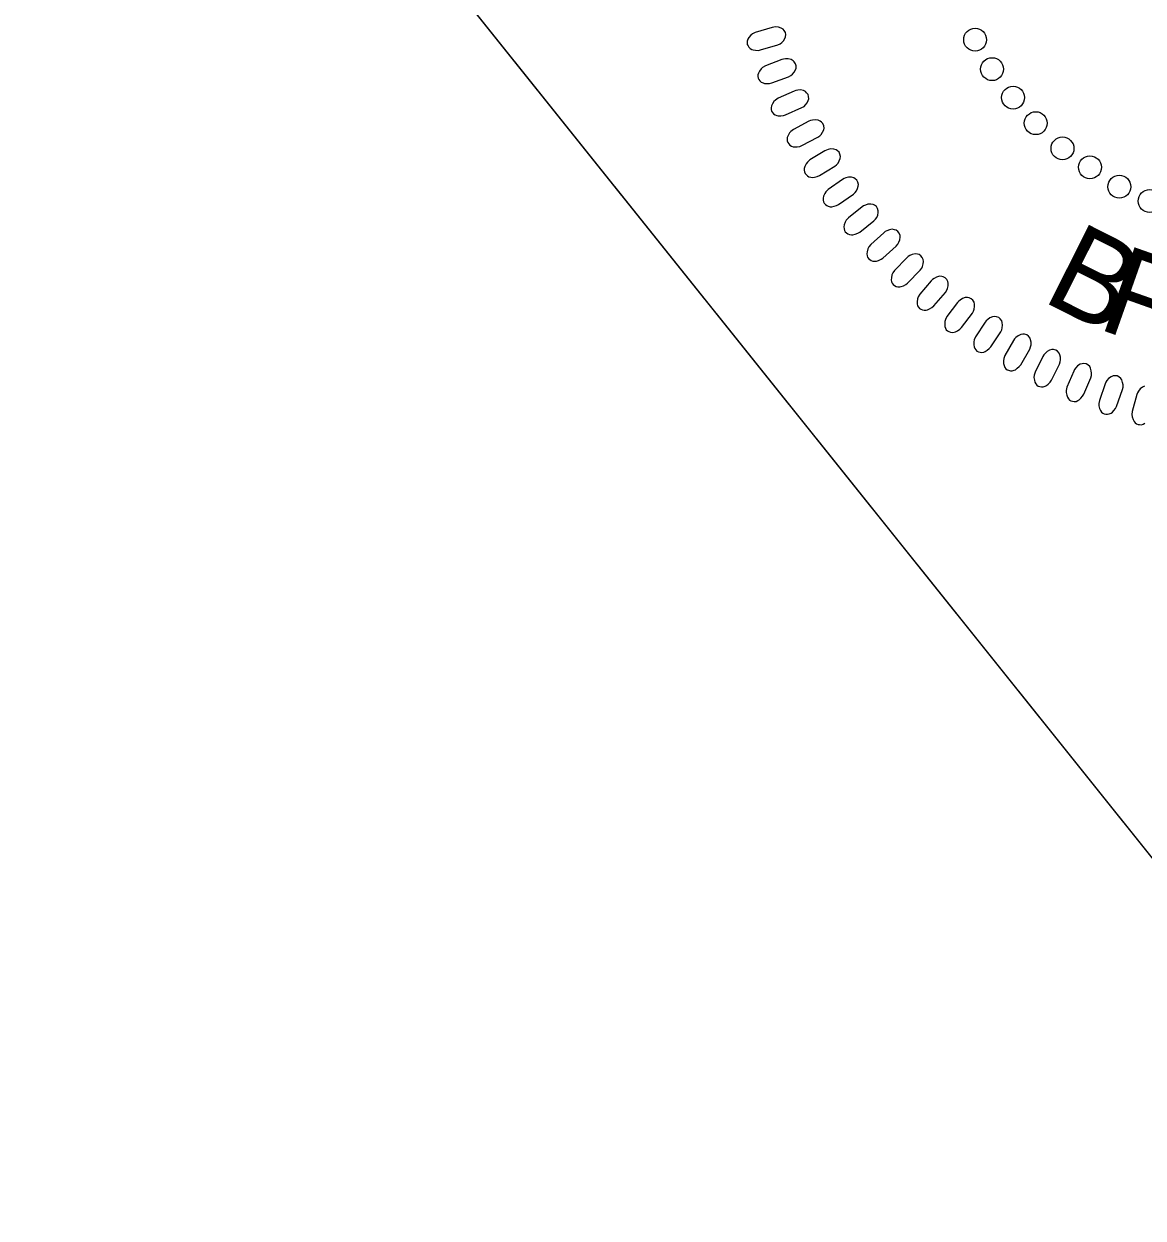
# Model space of a CAD drawing. Extents: x 473546 to 475544, y 505920 to 507827.
# Drawn here: x 474718.5 to 474796.9, y 507532.4 to 507616 of the extents above; entities that cross this region are included whole.
import ezdxf

# ---------------------------------------------------------------- set-up
doc = ezdxf.new("R2010")
doc.units = 0
for name, color, linetype in [('Sheet Clip Boundary CELL', 7, 'Continuous'), ('Sheet Plan CELL', 7, 'Continuous'), ('Sheet Profile Grid Minor CELL', 7, 'Continuous')]:
    doc.layers.add(name, color=color, linetype=linetype)

msp = doc.modelspace()

# ---------------------------------------------------------------- linework, layer by layer
at = {"layer": 'Sheet Clip Boundary CELL'}
msp.add_lwpolyline([(474813.139, 507538.121), (474704.643, 507673.668), (473746.994, 506907.144), (474401.701, 506086.253), (475384.175, 506871.789), (475333.837, 506934.746), (475466.728, 507040.999), (474969.31, 507663.123)], close=True, dxfattribs=at)
at = {"layer": 'Sheet Plan CELL'}
msp.add_lwpolyline([(474728.157, 507644.284), (474806.271, 507706.801), (474876.574, 507618.957), (474798.455, 507556.468)], close=True, dxfattribs=at)
at = {"layer": 'Sheet Profile Grid Minor CELL'}
for points in [[(474770.907, 507615.766), (474769.735, 507615.407), (474769.536, 507615.306), (474769.418, 507615.216), (474769.288, 507615.059), (474769.212, 507614.934), (474769.169, 507614.803), (474769.162, 507614.691), (474769.175, 507614.578), (474769.227, 507614.477), (474769.291, 507614.371), (474769.378, 507614.289), (474769.504, 507614.218), (474769.598, 507614.184), (474769.761, 507614.164), (474769.95, 507614.16), (474770.109, 507614.185), (474771.313, 507614.546), (474771.468, 507614.617), (474771.589, 507614.701), (474771.715, 507614.833), (474771.816, 507614.982), (474771.863, 507615.098), (474771.875, 507615.266), (474771.85, 507615.414), (474771.768, 507615.545), (474771.689, 507615.631), (474771.557, 507615.723), (474771.36, 507615.787), (474771.168, 507615.799), (474771.035, 507615.79)], [(474771.592, 507613.51), (474770.444, 507613.077), (474770.252, 507612.964), (474770.139, 507612.867), (474770.02, 507612.702), (474769.952, 507612.572), (474769.917, 507612.439), (474769.916, 507612.328), (474769.938, 507612.215), (474769.996, 507612.118), (474770.066, 507612.016), (474770.158, 507611.94), (474770.289, 507611.876), (474770.385, 507611.849), (474770.549, 507611.838), (474770.737, 507611.846), (474770.894, 507611.881), (474772.073, 507612.317), (474772.224, 507612.398), (474772.339, 507612.49), (474772.456, 507612.63), (474772.547, 507612.784), (474772.588, 507612.903), (474772.589, 507613.071), (474772.554, 507613.218), (474772.464, 507613.344), (474772.381, 507613.423), (474772.243, 507613.508), (474772.042, 507613.56), (474771.85, 507613.559), (474771.718, 507613.542)], [(474772.451, 507611.309), (474771.332, 507610.804), (474771.148, 507610.68), (474771.041, 507610.576), (474770.933, 507610.404), (474770.873, 507610.27), (474770.846, 507610.135), (474770.853, 507610.023), (474770.881, 507609.912), (474770.945, 507609.819), (474771.022, 507609.722), (474771.119, 507609.651), (474771.253, 507609.597), (474771.35, 507609.575), (474771.515, 507609.575), (474771.703, 507609.594), (474771.857, 507609.639), (474773.006, 507610.148), (474773.152, 507610.239), (474773.26, 507610.337), (474773.369, 507610.484), (474773.45, 507610.643), (474773.483, 507610.765), (474773.473, 507610.933), (474773.43, 507611.077), (474773.332, 507611.197), (474773.244, 507611.272), (474773.101, 507611.347), (474772.897, 507611.387), (474772.706, 507611.374), (474772.575, 507611.348)], [(474773.486, 507609.197), (474772.402, 507608.624), (474772.225, 507608.488), (474772.126, 507608.377), (474772.028, 507608.198), (474771.977, 507608.061), (474771.959, 507607.924), (474771.972, 507607.814), (474772.007, 507607.705), (474772.077, 507607.616), (474772.159, 507607.524), (474772.261, 507607.459), (474772.398, 507607.413), (474772.497, 507607.398), (474772.661, 507607.408), (474772.847, 507607.439), (474772.999, 507607.493), (474774.114, 507608.074), (474774.253, 507608.173), (474774.355, 507608.279), (474774.454, 507608.432), (474774.526, 507608.596), (474774.55, 507608.72), (474774.53, 507608.886), (474774.478, 507609.028), (474774.373, 507609.142), (474774.28, 507609.21), (474774.132, 507609.277), (474773.927, 507609.303), (474773.736, 507609.279), (474773.607, 507609.244)], [(474774.604, 507607.127), (474773.558, 507606.487), (474773.39, 507606.341), (474773.298, 507606.224), (474773.212, 507606.039), (474773.169, 507605.899), (474773.159, 507605.762), (474773.18, 507605.652), (474773.222, 507605.545), (474773.297, 507605.461), (474773.385, 507605.374), (474773.491, 507605.316), (474773.631, 507605.279), (474773.73, 507605.27), (474773.893, 507605.29), (474774.077, 507605.333), (474774.225, 507605.397), (474775.301, 507606.046), (474775.434, 507606.154), (474775.529, 507606.265), (474775.618, 507606.424), (474775.679, 507606.593), (474775.696, 507606.718), (474775.666, 507606.883), (474775.604, 507607.021), (474775.492, 507607.127), (474775.395, 507607.191), (474775.244, 507607.247), (474775.037, 507607.261), (474774.848, 507607.224), (474774.723, 507607.182)], [(474775.845, 507605.118), (474774.841, 507604.414), (474774.683, 507604.257), (474774.598, 507604.134), (474774.524, 507603.945), (474774.489, 507603.802), (474774.489, 507603.665), (474774.516, 507603.556), (474774.564, 507603.453), (474774.645, 507603.373), (474774.739, 507603.292), (474774.847, 507603.24), (474774.989, 507603.212), (474775.089, 507603.209), (474775.25, 507603.24), (474775.431, 507603.294), (474775.575, 507603.367), (474776.608, 507604.083), (474776.734, 507604.199), (474776.822, 507604.315), (474776.901, 507604.481), (474776.951, 507604.652), (474776.961, 507604.778), (474776.92, 507604.941), (474776.85, 507605.075), (474776.732, 507605.174), (474776.63, 507605.231), (474776.476, 507605.278), (474776.269, 507605.278), (474776.083, 507605.231), (474775.96, 507605.18)], [(474777.213, 507603.202), (474776.255, 507602.435), (474776.107, 507602.269), (474776.03, 507602.141), (474775.968, 507601.948), (474775.943, 507601.803), (474775.951, 507601.666), (474775.985, 507601.559), (474776.039, 507601.459), (474776.125, 507601.384), (474776.223, 507601.309), (474776.335, 507601.265), (474776.478, 507601.246), (474776.578, 507601.249), (474776.737, 507601.289), (474776.914, 507601.355), (474777.053, 507601.437), (474778.039, 507602.216), (474778.157, 507602.339), (474778.238, 507602.462), (474778.307, 507602.632), (474778.346, 507602.806), (474778.348, 507602.932), (474778.296, 507603.092), (474778.218, 507603.221), (474778.094, 507603.313), (474777.989, 507603.363), (474777.832, 507603.401), (474777.625, 507603.388), (474777.443, 507603.328), (474777.323, 507603.271)], [(474778.727, 507601.394), (474777.818, 507600.569), (474777.681, 507600.394), (474777.613, 507600.261), (474777.563, 507600.064), (474777.547, 507599.918), (474777.563, 507599.781), (474777.604, 507599.678), (474777.665, 507599.581), (474777.755, 507599.512), (474777.858, 507599.443), (474777.972, 507599.406), (474778.117, 507599.396), (474778.216, 507599.405), (474778.371, 507599.456), (474778.545, 507599.532), (474778.678, 507599.622), (474779.613, 507600.462), (474779.724, 507600.593), (474779.796, 507600.72), (474779.854, 507600.894), (474779.882, 507601.07), (474779.876, 507601.196), (474779.815, 507601.352), (474779.729, 507601.476), (474779.599, 507601.56), (474779.492, 507601.604), (474779.332, 507601.631), (474779.127, 507601.606), (474778.948, 507601.535), (474778.832, 507601.47)], [(474780.343, 507599.638), (474779.488, 507598.757), (474779.363, 507598.574), (474779.302, 507598.437), (474779.265, 507598.237), (474779.258, 507598.091), (474779.283, 507597.955), (474779.331, 507597.854), (474779.398, 507597.761), (474779.492, 507597.698), (474779.598, 507597.636), (474779.715, 507597.606), (474779.86, 507597.605), (474779.959, 507597.621), (474780.11, 507597.681), (474780.279, 507597.768), (474780.406, 507597.867), (474781.287, 507598.763), (474781.388, 507598.9), (474781.453, 507599.032), (474781.5, 507599.209), (474781.517, 507599.387), (474781.503, 507599.512), (474781.432, 507599.665), (474781.338, 507599.783), (474781.203, 507599.859), (474781.094, 507599.895), (474780.933, 507599.913), (474780.729, 507599.874), (474780.556, 507599.792), (474780.444, 507599.72)], [(474782.056, 507598.03), (474781.259, 507597.098), (474781.145, 507596.907), (474781.093, 507596.768), (474781.068, 507596.565), (474781.071, 507596.419), (474781.104, 507596.285), (474781.158, 507596.187), (474781.23, 507596.099), (474781.328, 507596.041), (474781.439, 507595.987), (474781.557, 507595.963), (474781.701, 507595.972), (474781.799, 507595.993), (474781.947, 507596.063), (474782.11, 507596.161), (474782.23, 507596.267), (474783.053, 507597.217), (474783.145, 507597.361), (474783.203, 507597.496), (474783.238, 507597.675), (474783.244, 507597.855), (474783.222, 507597.978), (474783.141, 507598.125), (474783.04, 507598.238), (474782.901, 507598.305), (474782.789, 507598.335), (474782.628, 507598.342), (474782.427, 507598.291), (474782.258, 507598.198), (474782.152, 507598.119)], [(474783.894, 507596.502), (474783.156, 507595.522), (474783.055, 507595.324), (474783.012, 507595.181), (474783, 507594.978), (474783.011, 507594.832), (474783.053, 507594.701), (474783.113, 507594.606), (474783.191, 507594.523), (474783.292, 507594.471), (474783.405, 507594.424), (474783.525, 507594.408), (474783.669, 507594.425), (474783.765, 507594.453), (474783.908, 507594.532), (474784.064, 507594.64), (474784.178, 507594.753), (474784.939, 507595.753), (474785.023, 507595.902), (474785.071, 507596.041), (474785.095, 507596.222), (474785.09, 507596.401), (474785.06, 507596.523), (474784.97, 507596.666), (474784.863, 507596.771), (474784.719, 507596.829), (474784.606, 507596.852), (474784.444, 507596.849), (474784.247, 507596.785), (474784.085, 507596.682), (474783.984, 507596.596)], [(474785.831, 507595.128), (474785.157, 507594.103), (474785.068, 507593.899), (474785.034, 507593.754), (474785.035, 507593.55), (474785.056, 507593.405), (474785.106, 507593.277), (474785.171, 507593.186), (474785.254, 507593.108), (474785.358, 507593.063), (474785.475, 507593.022), (474785.595, 507593.015), (474785.737, 507593.041), (474785.831, 507593.074), (474785.969, 507593.162), (474786.118, 507593.279), (474786.225, 507593.4), (474786.922, 507594.446), (474786.996, 507594.6), (474787.035, 507594.741), (474787.048, 507594.923), (474787.031, 507595.102), (474786.994, 507595.222), (474786.895, 507595.358), (474786.781, 507595.457), (474786.635, 507595.506), (474786.52, 507595.522), (474786.359, 507595.509), (474786.166, 507595.432), (474786.011, 507595.32), (474785.915, 507595.227)], [(474787.822, 507593.855), (474787.213, 507592.79), (474787.136, 507592.58), (474787.112, 507592.433), (474787.125, 507592.231), (474787.156, 507592.087), (474787.214, 507591.962), (474787.284, 507591.876), (474787.372, 507591.803), (474787.478, 507591.765), (474787.598, 507591.731), (474787.718, 507591.731), (474787.858, 507591.766), (474787.95, 507591.806), (474788.083, 507591.902), (474788.223, 507592.028), (474788.322, 507592.156), (474788.952, 507593.243), (474789.017, 507593.401), (474789.047, 507593.545), (474789.049, 507593.728), (474789.02, 507593.905), (474788.976, 507594.022), (474788.869, 507594.152), (474788.749, 507594.244), (474788.6, 507594.283), (474788.484, 507594.291), (474788.324, 507594.268), (474788.137, 507594.18), (474787.989, 507594.058), (474787.899, 507593.96)], [(474789.873, 507592.731), (474789.332, 507591.63), (474789.269, 507591.417), (474789.254, 507591.268), (474789.281, 507591.066), (474789.32, 507590.925), (474789.385, 507590.804), (474789.462, 507590.722), (474789.553, 507590.655), (474789.663, 507590.624), (474789.784, 507590.598), (474789.904, 507590.605), (474790.042, 507590.649), (474790.13, 507590.694), (474790.257, 507590.798), (474790.389, 507590.934), (474790.48, 507591.067), (474791.041, 507592.191), (474791.095, 507592.354), (474791.116, 507592.498), (474791.106, 507592.681), (474791.068, 507592.856), (474791.015, 507592.971), (474790.9, 507593.094), (474790.775, 507593.178), (474790.623, 507593.207), (474790.507, 507593.208), (474790.349, 507593.175), (474790.168, 507593.075), (474790.027, 507592.944), (474789.944, 507592.841)], [(474792.034, 507591.708), (474791.563, 507590.575), (474791.513, 507590.358), (474791.508, 507590.209), (474791.546, 507590.01), (474791.594, 507589.87), (474791.667, 507589.754), (474791.749, 507589.677), (474791.845, 507589.616), (474791.956, 507589.592), (474792.078, 507589.574), (474792.197, 507589.588), (474792.332, 507589.641), (474792.418, 507589.691), (474792.537, 507589.803), (474792.661, 507589.946), (474792.744, 507590.085), (474793.233, 507591.243), (474793.277, 507591.408), (474793.288, 507591.554), (474793.267, 507591.736), (474793.217, 507591.907), (474793.158, 507592.019), (474793.036, 507592.134), (474792.905, 507592.21), (474792.752, 507592.23), (474792.636, 507592.224), (474792.481, 507592.181), (474792.305, 507592.07), (474792.174, 507591.93), (474792.097, 507591.822)], [(474794.233, 507590.811), (474793.834, 507589.65), (474793.798, 507589.431), (474793.802, 507589.282), (474793.853, 507589.085), (474793.909, 507588.95), (474793.99, 507588.838), (474794.076, 507588.766), (474794.176, 507588.711), (474794.288, 507588.694), (474794.411, 507588.683), (474794.529, 507588.705), (474794.661, 507588.766), (474794.743, 507588.822), (474794.855, 507588.942), (474794.97, 507589.092), (474795.043, 507589.235), (474795.458, 507590.421), (474795.492, 507590.589), (474795.494, 507590.736), (474795.462, 507590.916), (474795.401, 507591.084), (474795.335, 507591.191), (474795.206, 507591.299), (474795.071, 507591.366), (474794.917, 507591.377), (474794.802, 507591.364), (474794.649, 507591.311), (474794.481, 507591.189), (474794.359, 507591.041), (474794.289, 507590.928)]]:
    msp.add_lwpolyline(points, close=True, dxfattribs=at)
msp.add_lwpolyline([(474796.997, 507590.654), (474796.847, 507590.592), (474796.688, 507590.46), (474796.575, 507590.304), (474796.512, 507590.188), (474796.463, 507590.067), (474796.139, 507588.883), (474796.117, 507588.662), (474796.129, 507588.513), (474796.193, 507588.32), (474796.258, 507588.189), (474796.345, 507588.082), (474796.435, 507588.016), (474796.539, 507587.966), (474796.651, 507587.956), (474796.775, 507587.954), (474796.892, 507587.984), (474797.019, 507588.052)], dxfattribs=at)
for centre in [(474785.131, 507614.905), (474786.319, 507612.845), (474787.79, 507610.853), (474789.376, 507609.061), (474791.248, 507607.293), (474793.17, 507605.974), (474795.229, 507604.611), (474797.356, 507603.609)]:
    msp.add_circle(centre, 0.801, dxfattribs=at)

# ---------------------------------------------------------------- texts
for s, rotation, p in [('B', 333.26092, (474789.687, 507596.68)), ('R', 340.53595, (474793.573, 507594.723))]:
    msp.add_text(s, height=6.236, rotation=rotation, dxfattribs=at).set_placement(p)

doc.saveas('drawing.dxf')
